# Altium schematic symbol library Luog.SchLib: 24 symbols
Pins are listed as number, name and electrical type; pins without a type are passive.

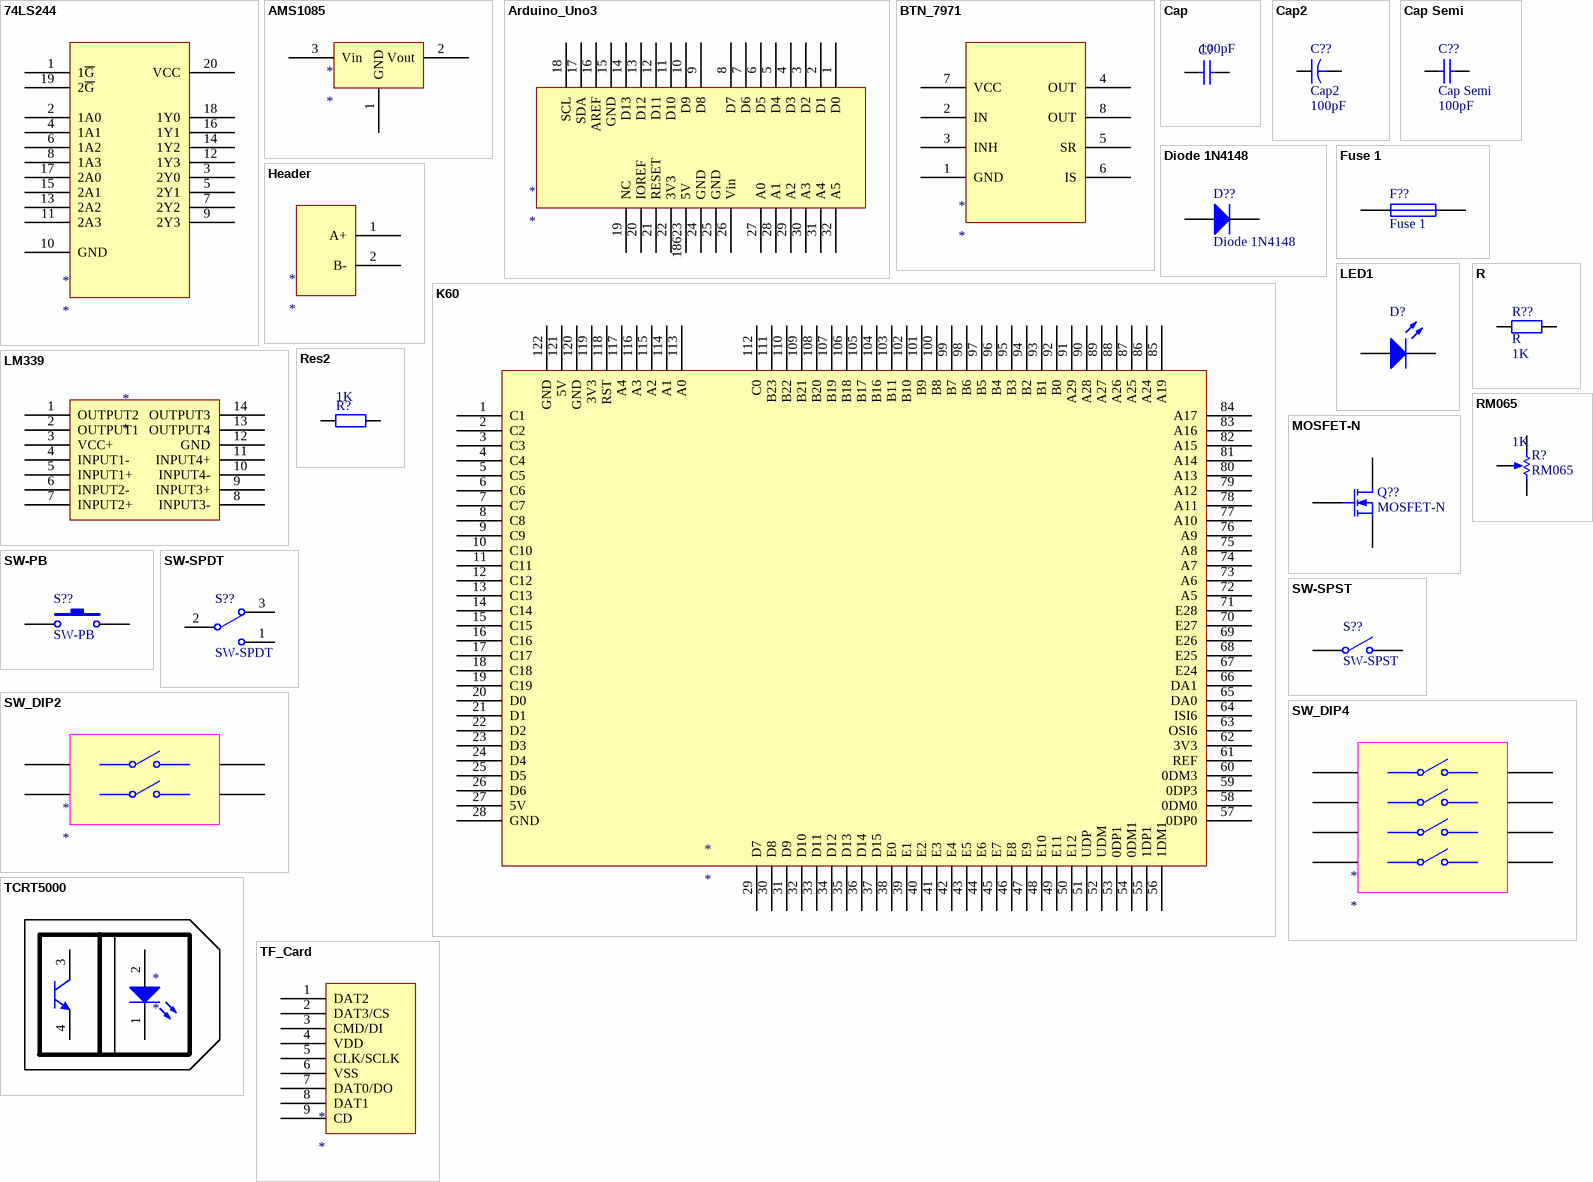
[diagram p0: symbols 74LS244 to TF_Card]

## 74LS244
designator *
footprint 74ALS244
footprint M74LS244C1R
pins: 1 1~{G}, 2 1A0, 3 2Y0, 4 1A1, 5 2Y1, 6 1A2, 7 2Y2, 8 1A3, 9 2Y3, 10 GND, 11 2A3, 12 1Y3, 13 2A2, 14 1Y2, 15 2A1, 16 1Y1, 17 2A0, 18 1Y0, 19 2~{G}, 20 VCC

## AMS1085
designator *
footprint AMS 1085CD
footprint TO-263-3L
pins: 1 GND, 2 Vout, 3 Vin

## Arduino_Uno3
designator *
footprint ARDUINO_UNO3
pins: 1 D0, 2 D1, 3 D2, 4 D3, 5 D4, 6 D5, 7 D6, 8 D7, 9 D8, 10 D9, 11 D10, 12 D11, 13 D12, 14 D13, 15 GND, 16 AREF, 17 SDA, 18 SCL, 19 NC, 20 IOREF, 21 RESET, 22 3V3, 24 GND, 25 GND, 26 Vin, 27 A0, 28 A1, 29 A2, 30 A3, 31 A4, 32 A5, 18623 5V

## BTN_7971
designator *
footprint BTN_7971B
pins: 1 GND, 2 IN, 3 INH, 4 OUT, 5 SR, 6 IS, 7 VCC, 8 OUT

## Cap
designator C?  value 100pF
Capacitor
footprint 0805
pins: 1, 2

## Cap2
designator C??  value 100pF
Capacitor
simulation model CAP (Capacitor)
signal-integrity model Cap
pins: 1, 2

## Cap Semi
designator C??  value 100pF
Capacitor (Semiconductor SIM Model)
footprint C1206 (Chip Capacitor, Body 3.2x1.6mm, IPC High Density)
footprint 0402 (Chip Capacitor, Body 1.0x0.5mm, IPC High Density)
footprint C2512 (Chip Capacitor, Body 2.54x1.27mm, IPC High Density)
footprint 1608[0603] (Chip Capacitor, Body 1.6x0.8mm, IPC High Density)
footprint C1210 (Chip Capacitor, Body 3.2x2.5mm, IPC High Density)
simulation model CAP (Semiconductor Capacitor)
signal-integrity model Cap Semi
pins: 1, 2

## Diode 1N4148
designator D??
High Conductance Fast Diode
footprint DO-35 (Diode, Axial; Body 3.8 x 1.9 mm (LxDia. max), Lead Dia. 0.53 mm (max))
simulation model 1N4148 (DIODE)
signal-integrity model 1N4148
footprint LL-34
pins: 1 A, 2 K

## Fuse 1
designator F??
Fuse
simulation model FUSE (Spice Subcircuit)
footprint 保险丝  15A
pins: 1, 2

## Header
designator *
footprint Header
pins: 1 A+, 2 B-

## K60
designator *
footprint K60
pins: 1 C1, 2 C2, 3 C3, 4 C4, 5 C5, 6 C6, 7 C7, 8 C8, 9 C9, 10 C10, 11 C11, 12 C12, 13 C13, 14 C14, 15 C15, 16 C16, 17 C17, 18 C18, 19 C19, 20 D0, 21 D1, 22 D2, 23 D3, 24 D4, 25 D5, 26 D6, 27 5V, 28 GND, 29 D7, 30 D8, 31 D9, 32 D10, 33 D11, 34 D12, 35 D13, 36 D14, 37 D15, 38 E0, 39 E1, 40 E2, 41 E3, 42 E4, 43 E5, 44 E6, 45 E7, 46 E8, 47 E9, 48 E10, 49 E11, 50 E12, 51 UDP, 52 UDM, 53 0DP1, 54 0DM1, 55 1DP1, 56 1DM1, 57 0DP0, 58 0DM0, 59 0DP3, 60 0DM3, 61 REF, 62 3V3, 63 OSI6, 64 ISI6, 65 DA0, 66 DA1, 67 E24, 68 E25, 69 E26, 70 E27, 71 E28, 72 A5, 73 A6, 74 A7, 75 A8, 76 A9, 77 A10, 78 A11, 79 A12, 80 A13, 81 A14, 82 A15, 83 A16, 84 A17, 85 A19, 86 A24, 87 A25, 88 A26, 89 A27, 90 A28, 91 A29, 92 B0, 93 B1, 94 B2, 95 B3, 96 B4, 97 B5, 98 B6, 99 B7, 100 B8, 101 B9, 102 B10, 103 B11, 104 B16, 105 B17, 106 B18, 107 B19, 108 B20, 109 B21, 110 B22, 111 B23, 112 C0, 113 A0, 114 A1, 115 A2, 116 A3, 117 A4, 118 RST, 119 3V3, 120 GND, 121 5V, 122 GND

## LED1
designator D?
Typical RED GaAs LED
footprint LED-0 (Typical INFRARED GaAs LED; 2 Leads)
pins: 1 A, 2 K

## LM339
designator *
footprint LM339
pins: 1 OUTPUT2, 2 OUTPUT1, 3 VCC+, 4 INPUT1-, 5 INPUT1+, 6 INPUT2-, 7 INPUT2+, 8 INPUT3-, 9 INPUT3+, 10 INPUT4-, 11 INPUT4+, 12 GND, 13 OUTPUT4, 14 OUTPUT3

## MOSFET-N
designator Q??
N-Channel MOSFET
simulation model NMOS (MOSFET-N)
footprint IRLR7843
pins: 1 G, 3 S, 4 D

## R
designator R??  value 1K
Resistor
simulation model RESISTOR (Resistor)
signal-integrity model Res
footprint R  0805
pins: 1, 2

## Res2
designator R?  value 1K
Resistor
footprint 0805
pins: 1, 2

## RM065
designator R?  value 1K
Potentiometer; Sim Note: Enter the Resistance value and the set point into parameter fields.; Set Position: 0.5
footprint RM065
pins: 1 TOP, 2 BOT, 3 TAP
1 alternate drawing of the same symbol

## SW-PB
designator S??
Switch
footprint SW_PB
pins: 1, 2

## SW-SPDT
designator S??
SPDT Subminiature Toggle Switch, Right Angle Mounting, Vertical Actuation
footprint BK1
pins: 1, 2, 3

## SW-SPST
designator S??
Single-Pole, Single-Throw Switch
pins: 1 COMMON, 2 NO

## SW_DIP2
designator *
footprint SW_DIP2
pins: 1 K1, 2 K2, 3 K2, 4 K1

## SW_DIP4
designator *
footprint SW_DIP4
footprint SW_CHIP4
pins: 1 K1, 2 K2, 3 K3, 4 K4, 5 K4, 6 K3, 7 K2, 8 K1

## TCRT5000
designator *
footprint TRCT5000
pins: 1 K, 2 A, 3 C, 4 E

## TF_Card
designator *
footprint TF
pins: 1 DAT2, 2 DAT3/CS, 3 CMD/DI, 4 VDD, 5 CLK/SCLK, 6 VSS, 7 DAT0/DO, 8 DAT1, 9 CD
